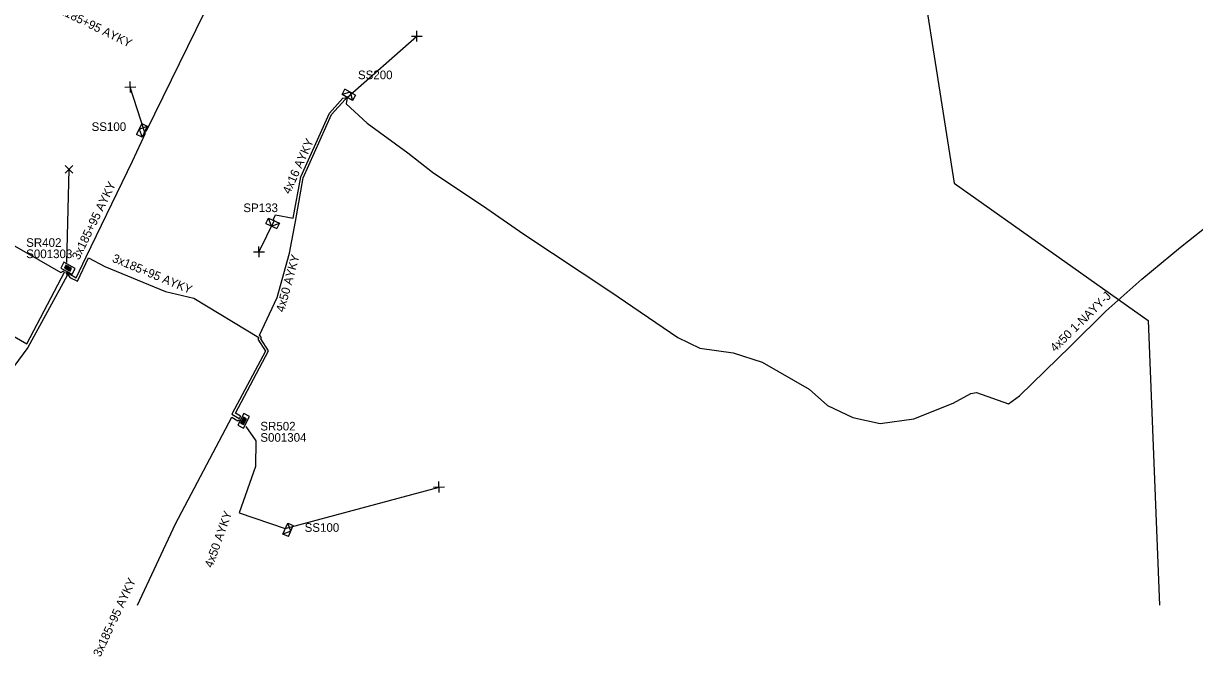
# Model space of a CAD drawing. Extents: x -762500 to -761285, y -1155006 to -1154135.
# Drawn here: x -762044.9 to -761909.8, y -1155005.9 to -1154932.9 of the extents above; entities that cross this region are included whole.
import ezdxf

# ---------------------------------------------------------------- set-up
doc = ezdxf.new("R2010")
doc.units = 0
for name, color, linetype in [('Vrstva 28', 7, 'Continuous'), ('Vrstva 29', 7, 'Continuous'), ('Vrstva 30', 7, 'Continuous'), ('Vrstva 31', 7, 'Continuous'), ('Vrstva 33', 7, 'Continuous'), ('Vrstva 34', 7, 'Continuous'), ('Vrstva 5', 7, 'Continuous'), ('Vrstva 52', 7, 'Continuous'), ('Vrstva 54', 7, 'Continuous'), ('Vrstva 59', 7, 'Continuous'), ('Vrstva 6', 7, 'Continuous')]:
    doc.layers.add(name, color=color, linetype=linetype)

msp = doc.modelspace()

# ---------------------------------------------------------------- linework, layer by layer
at = {"layer": 'Vrstva 28'}
for points in [[(-762040.233, -1154960.458), (-762040.586, -1154961.12)], [(-762040.586, -1154961.12), (-762039.261, -1154961.824)], [(-762038.909, -1154961.162), (-762040.233, -1154960.458)], [(-762039.983, -1154960.805), (-762040.161, -1154961.139)], [(-762040.161, -1154961.139), (-762039.504, -1154961.488)], [(-762039.964, -1154960.869), (-762040.097, -1154961.119)], [(-762040.097, -1154961.119), (-762039.523, -1154961.424)], [(-762039.944, -1154960.933), (-762040.033, -1154961.1)], [(-762040.033, -1154961.1), (-762039.543, -1154961.36)], [(-762039.326, -1154961.154), (-762039.983, -1154960.805)], [(-762039.925, -1154960.997), (-762039.969, -1154961.08)], [(-762039.969, -1154961.08), (-762039.562, -1154961.296)], [(-762039.39, -1154961.174), (-762039.964, -1154960.869)], [(-762039.454, -1154961.193), (-762039.944, -1154960.933)], [(-762039.518, -1154961.213), (-762039.925, -1154960.997)], [(-762039.577, -1154961.235), (-762039.91, -1154961.058)], [(-762039.562, -1154961.296), (-762039.518, -1154961.213)], [(-762039.543, -1154961.36), (-762039.454, -1154961.193)], [(-762039.523, -1154961.424), (-762039.39, -1154961.174)], [(-762039.504, -1154961.488), (-762039.326, -1154961.154)], [(-762039.261, -1154961.824), (-762038.909, -1154961.162)], [(-762019.481, -1154977.918), (-762020.162, -1154979.255)], [(-762019.492, -1154978.343), (-762019.83, -1154979.006)], [(-762019.472, -1154978.407), (-762019.767, -1154978.986)], [(-762019.767, -1154978.986), (-762019.514, -1154979.114)], [(-762019.451, -1154978.47), (-762019.703, -1154978.965)], [(-762019.703, -1154978.965), (-762019.535, -1154979.051)], [(-762019.431, -1154978.534), (-762019.64, -1154978.944)], [(-762019.64, -1154978.944), (-762019.555, -1154978.987)], [(-762019.579, -1154978.929), (-762019.407, -1154978.592)], [(-762019.555, -1154978.987), (-762019.346, -1154978.577)], [(-762019.535, -1154979.051), (-762019.283, -1154978.556)], [(-762019.514, -1154979.114), (-762019.219, -1154978.535)], [(-762019.494, -1154979.595), (-762018.813, -1154978.259)], [(-762019.494, -1154979.178), (-762019.156, -1154978.515)], [(-762019.156, -1154978.515), (-762019.492, -1154978.343)], [(-762018.813, -1154978.259), (-762019.481, -1154977.918)], [(-762019.219, -1154978.535), (-762019.472, -1154978.407)], [(-762019.283, -1154978.556), (-762019.451, -1154978.47)], [(-762019.346, -1154978.577), (-762019.431, -1154978.534)], [(-762020.162, -1154979.255), (-762019.494, -1154979.595)], [(-762019.83, -1154979.006), (-762019.494, -1154979.178)]]:
    msp.add_lwpolyline(points, dxfattribs=at)
at = {"layer": 'Vrstva 31'}
for points in [[(-762006.575, -1154941.188), (-762006.915, -1154941.801), (-762008.139, -1154941.122), (-762007.8, -1154940.51)], [(-762007.188, -1154940.849), (-762008.139, -1154941.122)], [(-762006.575, -1154941.188), (-762007.8, -1154940.51)], [(-762007.188, -1154940.849), (-762006.915, -1154941.801)], [(-762031.248, -1154944.457), (-762031.84, -1154945.726)], [(-762031.248, -1154944.457), (-762030.614, -1154944.753), (-762031.205, -1154946.022), (-762031.84, -1154945.726)], [(-762031.544, -1154945.091), (-762030.614, -1154944.753)], [(-762031.544, -1154945.091), (-762031.205, -1154946.022)], [(-762016.913, -1154955.988), (-762016.617, -1154955.353), (-762015.348, -1154955.945), (-762015.644, -1154956.579)], [(-762016.913, -1154955.988), (-762015.644, -1154956.579)], [(-762016.278, -1154956.284), (-762016.617, -1154955.353)], [(-762016.278, -1154956.284), (-762015.348, -1154955.945)], [(-762014.326, -1154992.107), (-762014.965, -1154991.822), (-762014.396, -1154990.543), (-762013.756, -1154990.828)], [(-762014.041, -1154991.468), (-762014.396, -1154990.543)], [(-762014.326, -1154992.107), (-762013.756, -1154990.828)], [(-762014.041, -1154991.468), (-762014.965, -1154991.822)]]:
    msp.add_lwpolyline(points, dxfattribs=at)
at = {"layer": 'Vrstva 34'}
for points in [[(-762000.125, -1154934.391), (-761998.875, -1154934.369)], [(-761999.489, -1154935.005), (-761999.511, -1154933.755)], [(-762032.549, -1154940.875), (-762032.571, -1154939.625)], [(-762033.185, -1154940.261), (-762031.935, -1154940.239)], [(-762040.072, -1154949.308), (-762039.188, -1154950.192)], [(-762040.072, -1154950.192), (-762039.188, -1154949.308)], [(-762017.709, -1154959.875), (-762017.731, -1154958.625)], [(-762018.345, -1154959.261), (-762017.095, -1154959.239)], [(-761996.929, -1154987.005), (-761996.951, -1154985.755)], [(-761997.565, -1154986.391), (-761996.315, -1154986.369)]]:
    msp.add_lwpolyline(points, dxfattribs=at)
at = {"layer": 'Vrstva 5'}
for points in [[(-761956.44, -1154882.89), (-761955.96, -1154882.8), (-761951.69, -1154884.37), (-761949.77, -1154885.38), (-761947.36, -1154887.8), (-761947.58, -1154890.38), (-761943.02, -1154916.39), (-761937.53, -1154951.34), (-761915.13, -1154967.16), (-761913.82, -1155000)], [(-762039.75, -1154961.71), (-762039.47, -1154961.88), (-762038.8, -1154962.24), (-762037.67, -1154959.82), (-762032.32, -1154948.79), (-762030.82, -1154945.58), (-762030.91, -1154945.39), (-762030.69, -1154945.3), (-762024.01, -1154931.64)], [(-762019.88, -1154978.42), (-762019.86, -1154978.22), (-762020.44, -1154977.88), (-762016.61, -1154970.68), (-762017.51, -1154969.27), (-762017.43, -1154969.12), (-762017.64, -1154968.87), (-762015.61, -1154964.54), (-762014.19, -1154959.41), (-762013.52, -1154955.74), (-762012.61, -1154950.71), (-762009.34, -1154943.42), (-762007.79, -1154941.68), (-762007.53, -1154941.46)], [(-762015.98, -1154955.65), (-762016.05, -1154955.47), (-762015.8, -1154954.97), (-762013.77, -1154955.37), (-762012.89, -1154950.62), (-762009.59, -1154943.26), (-762008.04, -1154941.52), (-762007.53, -1154941.46)], [(-762048.48, -1154957.11), (-762040.57, -1154961.64), (-762040.21, -1154961.46)], [(-762039.87, -1154961.65), (-762039.53, -1154962.2), (-762038.66, -1154962.65), (-762037.4, -1154959.95), (-762035.48, -1154960.93), (-762028.51, -1154963.82), (-762025.23, -1154964.6), (-762017.75, -1154969.14), (-762017.83, -1154969.32), (-762016.95, -1154970.7), (-762020.84, -1154977.99), (-762019.94, -1154978.53)], [(-762039.98, -1154961.58), (-762039.86, -1154961.99), (-762044.4, -1154970.29), (-762056.02, -1154986.07), (-762056.62, -1154986), (-762056.37, -1154986.51), (-762065.89, -1154999.15), (-762066.62, -1154999.25)], [(-762056.96, -1154963.64), (-762056.61, -1154963.33), (-762050.84, -1154966.21), (-762044.51, -1154969.87), (-762040.1, -1154961.52)], [(-762031.73, -1155000), (-762027.36, -1154990.61), (-762020.85, -1154978.34), (-762020.15, -1154978.75), (-762020, -1154978.65)], [(-762019.24, -1154979.4), (-762018.06, -1154981.05), (-762018.1, -1154984), (-762020.01, -1154989.36), (-762014.68, -1154991.18)]]:
    msp.add_lwpolyline(points, dxfattribs=at)
at = {"layer": 'Vrstva 52'}
msp.add_lwpolyline([(-762007.53, -1154941.46), (-762007.66, -1154942.19), (-762005.24, -1154944.42), (-762000.54, -1154947.82), (-761997.69, -1154950.08), (-761991.43, -1154954.26), (-761987.17, -1154957.2), (-761977.12, -1154963.85), (-761969.38, -1154969.13), (-761966.87, -1154970.37), (-761963.03, -1154970.9), (-761959.66, -1154971.99), (-761954.24, -1154975.09), (-761952.13, -1154976.97), (-761949.2, -1154978.35), (-761946.06, -1154979.07), (-761942.17, -1154978.53), (-761937.64, -1154976.71), (-761935.61, -1154975.59), (-761934.96, -1154975.49), (-761931.24, -1154976.79), (-761929.98, -1154975.88), (-761924.1, -1154970.12), (-761920.01, -1154966.08), (-761915.86, -1154962.39), (-761911.4, -1154958.7), (-761907.53, -1154955.64)], dxfattribs=at)
at = {"layer": 'Vrstva 59'}
for points in [[(-762007.53, -1154941.46), (-761999.5, -1154934.38)], [(-762030.91, -1154945.39), (-762032.56, -1154940.25)], [(-762039.9, -1154960.48), (-762039.63, -1154949.75)], [(-762015.98, -1154955.65), (-762017.72, -1154959.25)], [(-762014.68, -1154991.18), (-761996.94, -1154986.38)]]:
    msp.add_lwpolyline(points, dxfattribs=at)

# ---------------------------------------------------------------- texts
at = {"layer": 'Vrstva 29'}
for s, p in [('S001303', (-762044.57, -1154959.98)), ('S001304', (-762017.56, -1154981.16))]:
    msp.add_text(s, height=0.9943, dxfattribs=at).set_placement(p)
at = {"layer": 'Vrstva 30'}
for s, p in [('SR402', (-762044.57, -1154958.68)), ('SR502', (-762017.56, -1154979.86))]:
    msp.add_text(s, height=0.9943, dxfattribs=at).set_placement(p)
at = {"layer": 'Vrstva 33'}
for s, p in [('SS200', (-762006.3, -1154939.34)), ('SS100', (-762037.03, -1154945.31)), ('SP133', (-762019.52, -1154954.67)), ('SS100', (-762012.45, -1154991.55))]:
    msp.add_text(s, height=0.9943, dxfattribs=at).set_placement(p)
at = {"layer": 'Vrstva 54'}
msp.add_text('4x50 1-NAYY-J', height=0.99429, rotation=44.40934, dxfattribs=at).set_placement((-761925.87, -1154970.87))
at = {"layer": 'Vrstva 6'}
for s, height, rotation, p in [('3x185+95 AYKY', 0.99428, 333.9438, (-762041.48, -1154931.42)), ('4x16 AYKY', 0.9943, 65.84708, (-762014.15, -1154952.67)), ('3x185+95 AYKY', 0.99429, 64.12472, (-762038.47, -1154960.27)), ('3x185+95 AYKY', 0.99428, 337.47943, (-762034.73, -1154960.37)), ('4x50 AYKY', 0.9943, 74.52774, (-762014.83, -1154966.28)), ('4x50 AYKY', 0.9943, 70.38682, (-762023.09, -1154995.77)), ('3x185+95 AYKY', 0.99429, 65.05561, (-762036.01, -1155006.05))]:
    msp.add_text(s, height=height, rotation=rotation, dxfattribs=at).set_placement(p)

doc.saveas('drawing.dxf')
